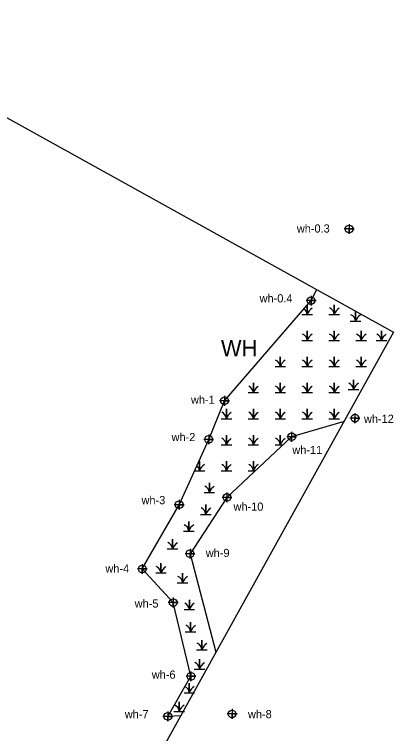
# Model space of a CAD drawing. Extents: x 2174810 to 2196950, y 76168 to 88270.
# Drawn here: x 2177531.1 to 2177762.5, y 78724.8 to 79164 of the extents above; entities that cross this region are included whole.
import ezdxf

# ---------------------------------------------------------------- set-up
doc = ezdxf.new("R2010")
doc.units = 0
for name, color, linetype in [('Default', 7, 'Continuous'), ('Exist Environmental Wetland Boundary', 7, 'Continuous'), ('Exist Environmental Wetland Boundary Cogo Number', 7, 'Continuous'), ('Exist Environmental Wetland Boundary Cogo Point CELL', 7, 'Continuous'), ('Exist Environmental Wetland Boundary Text', 7, 'Continuous'), ('Exist Hydro Swamp or Marsh', 7, 'Continuous')]:
    doc.layers.add(name, color=color, linetype=linetype)

msp = doc.modelspace()

# ---------------------------------------------------------------- linework, layer by layer
at = {"layer": 'Default'}
msp.add_lwpolyline([(2175864.96, 77468.65), (2175974.98, 78067.37), (2175948.66, 78270.55), (2176147, 78296.25), (2176199.64, 77889.88), (2176204.55, 77860.59), (2176211.62, 77831.74), (2176220.8, 77803.5), (2176232.06, 77776.01), (2176245.32, 77749.44), (2176260.52, 77723.93), (2176492.8, 77599.18), (2176546.77, 77667.81), (2176598.73, 77737.98), (2176648.61, 77809.64), (2176696.4, 77882.71), (2176742.03, 77957.15), (2176785.48, 78032.88), (2177412.72, 79163.99), (2177762.53, 78970.01), (2177135.29, 77838.9), (2177091.17, 77761.72), (2177045.03, 77685.72), (2176996.93, 77610.95)], dxfattribs=at)
at = {"layer": 'Exist Environmental Wetland Boundary'}
for points in [[(2177632.54, 78735.6), (2177624.76, 78735.3), (2177638.88, 78759.77), (2177628.01, 78804.81), (2177609.18, 78825.31), (2177631.68, 78864.58), (2177649.68, 78904.47), (2177659.34, 78928.03), (2177712.19, 78989.21), (2177715.77, 78995.94)], [(2177732.29, 78915.46), (2177700.31, 78906.05), (2177660.83, 78869.01), (2177638.29, 78834.65), (2177654.09, 78774.44)]]:
    msp.add_lwpolyline(points, dxfattribs=at)
at = {"layer": 'Exist Environmental Wetland Boundary Cogo Point CELL'}
for points in [[(2177735.42, 79035.93), (2177735.42, 79029.93), (2177735.42, 79032.93), (2177738.42, 79032.93), (2177732.42, 79032.93)], [(2177712.19, 78992.21), (2177712.19, 78986.21), (2177712.19, 78989.21), (2177715.19, 78989.21), (2177709.19, 78989.21)], [(2177659.34, 78931.03), (2177659.34, 78925.03), (2177659.34, 78928.03), (2177662.34, 78928.03), (2177656.34, 78928.03)], [(2177738.92, 78920.41), (2177738.92, 78914.41), (2177738.92, 78917.41), (2177741.92, 78917.41), (2177735.92, 78917.41)], [(2177700.31, 78909.05), (2177700.31, 78903.05), (2177700.31, 78906.05), (2177703.31, 78906.05), (2177697.31, 78906.05)], [(2177649.68, 78907.47), (2177649.68, 78901.47), (2177649.68, 78904.47), (2177652.68, 78904.47), (2177646.68, 78904.47)], [(2177660.83, 78872.01), (2177660.83, 78866.01), (2177660.83, 78869.01), (2177663.83, 78869.01), (2177657.83, 78869.01)], [(2177631.68, 78867.58), (2177631.68, 78861.58), (2177631.68, 78864.58), (2177634.68, 78864.58), (2177628.68, 78864.58)], [(2177638.29, 78837.65), (2177638.29, 78831.65), (2177638.29, 78834.65), (2177641.29, 78834.65), (2177635.29, 78834.65)], [(2177609.18, 78828.31), (2177609.18, 78822.31), (2177609.18, 78825.31), (2177612.18, 78825.31), (2177606.18, 78825.31)], [(2177628.01, 78807.81), (2177628.01, 78801.81), (2177628.01, 78804.81), (2177631.01, 78804.81), (2177625.01, 78804.81)], [(2177638.88, 78762.77), (2177638.88, 78756.77), (2177638.88, 78759.77), (2177641.88, 78759.77), (2177635.88, 78759.77)], [(2177624.76, 78738.3), (2177624.76, 78732.3), (2177624.76, 78735.3), (2177627.76, 78735.3), (2177621.76, 78735.3)], [(2177663.96, 78739.8), (2177663.96, 78733.8), (2177663.96, 78736.8), (2177666.96, 78736.8), (2177660.96, 78736.8)]]:
    msp.add_lwpolyline(points, dxfattribs=at)
for centre in [(2177735.42, 79032.93), (2177712.19, 78989.21), (2177659.34, 78928.03), (2177738.92, 78917.41), (2177700.31, 78906.05), (2177649.68, 78904.47), (2177660.83, 78869.01), (2177631.68, 78864.58), (2177638.29, 78834.65), (2177609.18, 78825.31), (2177628.01, 78804.81), (2177638.88, 78759.77), (2177624.76, 78735.3), (2177663.96, 78736.8)]:
    msp.add_circle(centre, 2.34, dxfattribs=at)
at = {"layer": 'Exist Hydro Swamp or Marsh'}
msp.add_line((2177663.64, 78933.02), (2177663.71, 78933.02), dxfattribs=at)
for points in [[(2177723.07, 78980.77), (2177726.29, 78980.77), (2177726.29, 78986.69), (2177726.29, 78980.77), (2177729.52, 78980.77)], [(2177706.62, 78980.77), (2177709.84, 78980.77), (2177709.84, 78986.49)], [(2177709.84, 78986.49), (2177709.84, 78980.77), (2177713.07, 78980.77)], [(2177736.12, 78976.63), (2177739.35, 78976.63), (2177739.35, 78982.55), (2177739.35, 78976.63), (2177742.57, 78976.63)], [(2177742.74, 78980.98), (2177742.74, 78980.77), (2177743.13, 78980.77)], [(2177706.62, 78964.85), (2177709.84, 78964.85), (2177709.84, 78970.77), (2177709.84, 78964.85), (2177713.07, 78964.85)], [(2177723.07, 78964.85), (2177726.29, 78964.85), (2177726.29, 78970.77), (2177726.29, 78964.85), (2177729.52, 78964.85)], [(2177739.52, 78964.85), (2177742.74, 78964.85), (2177742.74, 78970.77), (2177742.74, 78964.85), (2177745.97, 78964.85)], [(2177751.86, 78964.85), (2177755.08, 78964.85), (2177755.08, 78970.77), (2177755.08, 78964.85), (2177758.31, 78964.85)], [(2177690.16, 78948.93), (2177693.39, 78948.93), (2177693.39, 78954.85), (2177693.39, 78948.93), (2177696.62, 78948.93)], [(2177706.62, 78948.93), (2177709.84, 78948.93), (2177709.84, 78954.85), (2177709.84, 78948.93), (2177713.07, 78948.93)], [(2177723.07, 78948.93), (2177726.29, 78948.93), (2177726.29, 78954.85), (2177726.29, 78948.93), (2177729.52, 78948.93)], [(2177739.52, 78948.93), (2177742.74, 78948.93), (2177742.74, 78954.85), (2177742.74, 78948.93), (2177745.97, 78948.93)], [(2177673.71, 78933.02), (2177676.94, 78933.02), (2177676.94, 78938.93), (2177676.94, 78933.02), (2177680.16, 78933.02)], [(2177690.16, 78933.02), (2177693.39, 78933.02), (2177693.39, 78938.93), (2177693.39, 78933.02), (2177696.62, 78933.02)], [(2177706.62, 78933.02), (2177709.84, 78933.02), (2177709.84, 78938.93), (2177709.84, 78933.02), (2177713.07, 78933.02)], [(2177723.07, 78933.02), (2177726.29, 78933.02), (2177726.29, 78938.93), (2177726.29, 78933.02), (2177729.52, 78933.02)], [(2177734.84, 78934.87), (2177738.06, 78934.87), (2177738.06, 78940.79), (2177738.06, 78934.87), (2177741.29, 78934.87)], [(2177657.26, 78917.1), (2177660.49, 78917.1), (2177660.49, 78923.02), (2177660.49, 78917.1), (2177663.71, 78917.1)], [(2177673.71, 78917.1), (2177676.94, 78917.1), (2177676.94, 78923.02), (2177676.94, 78917.1), (2177680.16, 78917.1)], [(2177690.16, 78917.1), (2177693.39, 78917.1), (2177693.39, 78923.02), (2177693.39, 78917.1), (2177696.62, 78917.1)], [(2177706.62, 78917.1), (2177709.84, 78917.1), (2177709.84, 78923.02), (2177709.84, 78917.1), (2177713.07, 78917.1)], [(2177723.07, 78917.1), (2177726.29, 78917.1), (2177726.29, 78923.02), (2177726.29, 78917.1), (2177729.52, 78917.1)], [(2177657.26, 78901.18), (2177660.49, 78901.18), (2177660.49, 78907.1), (2177660.49, 78901.18), (2177663.71, 78901.18)], [(2177673.71, 78901.18), (2177676.94, 78901.18), (2177676.94, 78907.1), (2177676.94, 78901.18), (2177680.16, 78901.18)], [(2177690.16, 78901.18), (2177693.39, 78901.18), (2177693.39, 78907.1), (2177693.39, 78901.18), (2177695.12, 78901.18)], [(2177641.02, 78885.26), (2177644.04, 78885.26), (2177644.04, 78891.18), (2177644.04, 78885.26), (2177647.26, 78885.26)], [(2177657.26, 78885.26), (2177660.49, 78885.26), (2177660.49, 78891.18), (2177660.49, 78885.26), (2177663.71, 78885.26)], [(2177673.71, 78885.26), (2177676.94, 78885.26), (2177676.94, 78891.18), (2177676.94, 78885.26), (2177678.15, 78885.26)], [(2177646.87, 78872.02), (2177650.1, 78872.02), (2177650.1, 78877.93), (2177650.1, 78872.02), (2177653.32, 78872.02)], [(2177644.67, 78858.67), (2177647.89, 78858.67), (2177647.89, 78864.59), (2177647.89, 78858.67), (2177651.12, 78858.67)], [(2177634.28, 78848.38), (2177637.51, 78848.38), (2177637.51, 78854.3), (2177637.51, 78848.38), (2177640.73, 78848.38)], [(2177624.36, 78837.51), (2177627.58, 78837.51), (2177627.58, 78843.43), (2177627.58, 78837.51), (2177630.81, 78837.51)], [(2177644.04, 78843.41), (2177644.04, 78843.43), (2177644.04, 78843.41)], [(2177617.34, 78822.88), (2177620.56, 78822.88), (2177620.56, 78828.8), (2177620.56, 78822.88), (2177623.79, 78822.88)], [(2177630.49, 78816.84), (2177633.72, 78816.84), (2177633.72, 78822.76), (2177633.72, 78816.84), (2177636.94, 78816.84)], [(2177634.65, 78800.51), (2177637.87, 78800.51), (2177637.87, 78806.43), (2177637.87, 78800.51), (2177641.1, 78800.51)], [(2177635.37, 78786.98), (2177638.59, 78786.98), (2177638.59, 78792.9), (2177638.59, 78786.98), (2177641.82, 78786.98)], [(2177642.29, 78776.02), (2177645.52, 78776.02), (2177645.52, 78781.93), (2177645.52, 78776.02), (2177648.75, 78776.02)], [(2177640.81, 78764.22), (2177644.04, 78764.22), (2177644.04, 78770.14), (2177644.04, 78764.22), (2177647.26, 78764.22)], [(2177634.62, 78749.67), (2177637.84, 78749.67), (2177637.84, 78755.59), (2177637.84, 78749.67), (2177641.07, 78749.67)], [(2177628.43, 78738.32), (2177631.65, 78738.32), (2177631.65, 78744.24), (2177631.65, 78738.32), (2177634.88, 78738.32)]]:
    msp.add_lwpolyline(points, dxfattribs=at)
for centre, radius, start, end in [((2177705.24, 78980.44), 4.61, 4.1403, 55.1155), ((2177716.68, 78978.5), 7.21, 122.1274, 161.6222), ((2177721.69, 78980.44), 4.61, 4.1403, 67.535), ((2177733.13, 78978.5), 7.21, 122.1274, 161.6222), ((2177734.75, 78976.3), 4.61, 4.1403, 67.535), ((2177746.19, 78974.36), 7.21, 122.1274, 161.6222), ((2177738.14, 78980.44), 4.61, 4.1403, 6.9894), ((2177749.58, 78978.5), 7.21, 160.0989, 161.6222), ((2177705.24, 78964.52), 4.61, 4.1403, 67.535), ((2177716.68, 78962.58), 7.21, 122.1274, 161.6222), ((2177721.69, 78964.52), 4.61, 4.1403, 67.535), ((2177733.13, 78962.58), 7.21, 122.1274, 161.6222), ((2177738.14, 78964.52), 4.61, 4.1403, 67.535), ((2177749.58, 78962.58), 7.21, 122.1274, 161.6222), ((2177750.48, 78964.52), 4.61, 4.1403, 67.535), ((2177761.92, 78962.58), 7.21, 122.1274, 161.6222), ((2177688.79, 78948.6), 4.61, 4.1403, 67.535), ((2177700.23, 78946.66), 7.21, 122.1274, 161.6222), ((2177705.24, 78948.6), 4.61, 4.1403, 67.535), ((2177716.68, 78946.66), 7.21, 122.1274, 161.6222), ((2177721.69, 78948.6), 4.61, 4.1403, 67.535), ((2177733.13, 78946.66), 7.21, 122.1274, 161.6222), ((2177738.14, 78948.6), 4.61, 4.1403, 67.535), ((2177749.58, 78946.66), 7.21, 122.1274, 161.6222), ((2177733.46, 78934.54), 4.61, 4.1403, 67.535), ((2177744.9, 78932.6), 7.21, 122.1274, 161.6222), ((2177672.34, 78932.68), 4.61, 4.1403, 67.535), ((2177683.78, 78930.74), 7.21, 122.1274, 161.6222), ((2177688.79, 78932.68), 4.61, 4.1403, 67.535), ((2177700.23, 78930.74), 7.21, 122.1274, 161.6222), ((2177705.24, 78932.68), 4.61, 4.1403, 67.535), ((2177716.68, 78930.74), 7.21, 122.1274, 161.6222), ((2177721.69, 78932.68), 4.61, 4.1403, 67.535), ((2177733.13, 78930.74), 7.21, 122.1274, 161.6222), ((2177655.89, 78916.76), 4.61, 4.1403, 67.535), ((2177667.33, 78914.82), 7.21, 122.1274, 161.6222), ((2177672.34, 78916.76), 4.61, 4.1403, 67.535), ((2177683.78, 78914.82), 7.21, 122.1274, 161.6222), ((2177688.79, 78916.76), 4.61, 4.1403, 67.535), ((2177700.23, 78914.82), 7.21, 122.1274, 161.6222), ((2177705.24, 78916.76), 4.61, 4.1403, 67.535), ((2177716.68, 78914.82), 7.21, 122.1274, 161.6222), ((2177721.69, 78916.76), 4.61, 4.1403, 67.535), ((2177733.13, 78914.82), 7.21, 122.1274, 161.6222), ((2177655.89, 78900.85), 4.61, 4.1403, 67.535), ((2177667.33, 78898.91), 7.21, 122.1274, 161.6222), ((2177672.34, 78900.85), 4.61, 4.1403, 67.535), ((2177683.78, 78898.91), 7.21, 122.1274, 161.6222), ((2177688.79, 78900.85), 4.61, 4.1403, 67.535), ((2177700.23, 78898.91), 7.21, 122.1274, 161.6222), ((2177639.44, 78884.93), 4.61, 4.1403, 49.2957), ((2177650.88, 78882.99), 7.21, 122.1274, 161.6222), ((2177655.89, 78884.93), 4.61, 4.1403, 67.535), ((2177667.33, 78882.99), 7.21, 122.1274, 161.6222), ((2177672.34, 78884.93), 4.61, 4.1403, 67.535), ((2177683.78, 78882.99), 7.21, 122.1274, 161.6222), ((2177645.5, 78871.68), 4.61, 4.1403, 67.535), ((2177656.94, 78869.74), 7.21, 122.1274, 161.6222), ((2177643.29, 78858.34), 4.61, 4.1403, 67.535), ((2177654.73, 78856.4), 7.21, 122.1274, 161.6222), ((2177632.91, 78848.05), 4.61, 4.1403, 67.535), ((2177644.35, 78846.11), 7.21, 122.1274, 161.6222), ((2177622.98, 78837.18), 4.61, 4.1403, 67.535), ((2177634.43, 78835.24), 7.21, 122.1274, 161.6222), ((2177615.96, 78822.54), 4.61, 4.1403, 67.535), ((2177627.4, 78820.61), 7.21, 122.1274, 161.6222), ((2177629.12, 78816.51), 4.61, 4.1403, 67.535), ((2177640.56, 78814.57), 7.21, 122.1274, 161.6222), ((2177633.27, 78800.18), 4.61, 4.1403, 67.535), ((2177644.71, 78798.24), 7.21, 122.1274, 161.6222), ((2177633.99, 78786.65), 4.61, 4.1403, 67.535), ((2177645.44, 78784.71), 7.21, 122.1274, 161.6222), ((2177640.92, 78775.68), 4.61, 4.1403, 67.535), ((2177652.36, 78773.74), 7.21, 122.1274, 161.6222), ((2177639.44, 78763.89), 4.61, 4.1403, 67.535), ((2177650.88, 78761.95), 7.21, 122.1274, 161.6222), ((2177633.24, 78749.34), 4.61, 4.1403, 67.535), ((2177644.69, 78747.4), 7.21, 122.1274, 161.6222), ((2177627.05, 78737.99), 4.61, 4.1403, 67.535), ((2177638.49, 78736.05), 7.21, 122.1274, 161.6222)]:
    msp.add_arc(centre, radius, start, end, dxfattribs=at)

# ---------------------------------------------------------------- texts
at = {"layer": 'Exist Environmental Wetland Boundary Cogo Number'}
for s, p in [('wh-0.3', (2177703.49, 79030.74)), ('wh-0.4', (2177680.75, 78988.09)), ('wh-1', (2177638.87, 78926.18)), ('wh-12', (2177744.44, 78914.52)), ('wh-2', (2177627.02, 78903.38)), ('wh-11', (2177700.73, 78895.49)), ('wh-3', (2177608.69, 78864.85)), ('wh-10', (2177664.85, 78860.9)), ('wh-9', (2177647.9, 78832.59)), ('wh-4', (2177586.64, 78823.07)), ('wh-5', (2177604.51, 78801.72)), ('wh-6', (2177614.95, 78758.31)), ('wh-7', (2177598.48, 78734.17)), ('wh-8', (2177673.66, 78734.17))]:
    msp.add_text(s, height=5, dxfattribs=at).set_placement(p)
at = {"layer": 'Exist Environmental Wetland Boundary Text'}
msp.add_text('WH', height=10, dxfattribs=at).set_placement((2177657.15, 78955.22))

doc.saveas('drawing.dxf')
